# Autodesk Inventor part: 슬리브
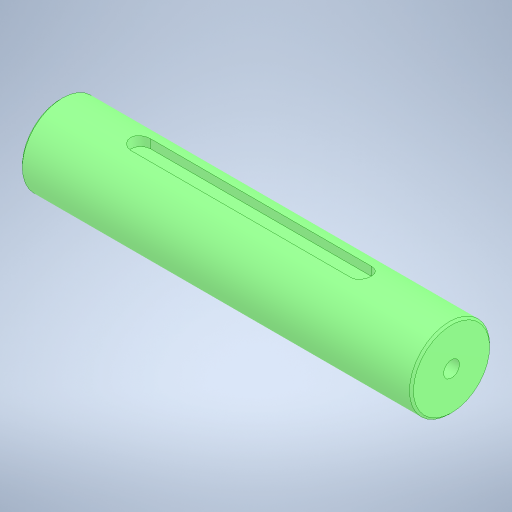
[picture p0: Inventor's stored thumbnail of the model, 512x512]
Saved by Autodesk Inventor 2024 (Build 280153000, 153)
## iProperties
Created: 2024-08
Part Number: 슬리브
Material: 강철, 탄소
Document SubType Name: Modeling
Designer: user
Density: 7.85 g/cm^3
Appearance: 반연마
Mass: 1682.78 g
Surface Area: 354.08 cm^2
Volume: 214.367 cm^3
Sending System: Autodesk Inventor 2025
Preprocessor: ST-DEVELOPER v20
Author: jhkim
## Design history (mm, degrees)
feature "솔리드1"
node "솔리드2"
